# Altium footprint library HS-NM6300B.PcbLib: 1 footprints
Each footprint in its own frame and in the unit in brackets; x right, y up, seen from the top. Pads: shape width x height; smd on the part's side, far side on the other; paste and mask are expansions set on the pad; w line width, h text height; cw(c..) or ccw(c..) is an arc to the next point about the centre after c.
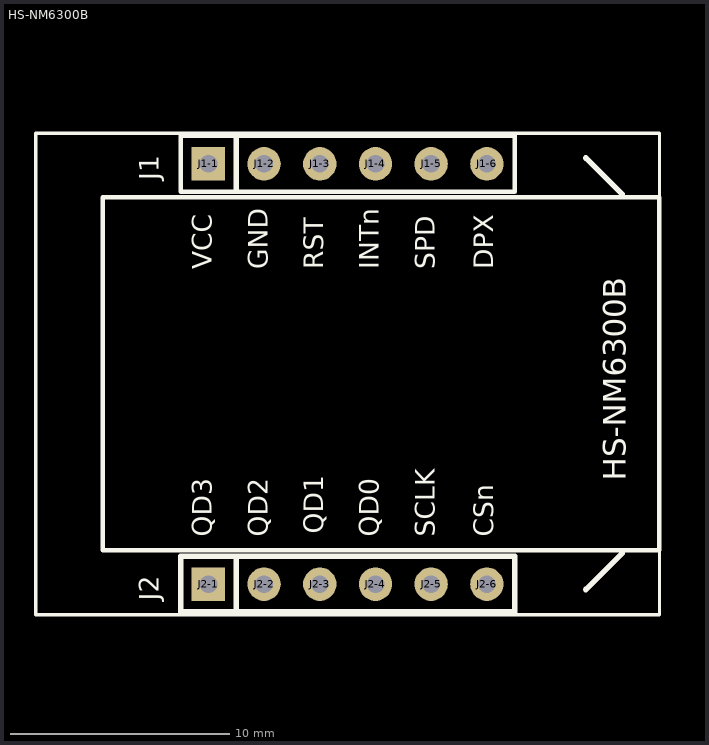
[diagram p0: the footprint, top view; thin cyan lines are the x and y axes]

## HS-NM6300B [mil]
pads (12):
  rect 60x60 hole 32: J1-1(-39967.9,-31115.46) J2-1(-39967.9,-31870.46)
  round 60 hole 32: J1-2(-39867.9,-31115.46) J1-3(-39767.9,-31115.46) J1-4(-39667.9,-31115.46) J1-5(-39567.9,-31115.46) J1-6(-39467.9,-31115.46) J2-2(-39867.9,-31870.46) J2-3(-39767.9,-31870.46) J2-4(-39667.9,-31870.46) J2-5(-39567.9,-31870.46) J2-6(-39467.9,-31870.46)
Top Overlay:
  lines w6: -40277.9,-31925.46 -40277.9,-31060.46 -39157.9,-31060.46 -39157.9,-31925.46 -40277.9,-31925.46
  lines w7.87: -40017.9,-31165.46 -40017.9,-31065.46 -39417.9,-31065.46 -39417.9,-31165.46 -40017.9,-31165.46
  lines w8: -40157.9,-31809.46 -40157.9,-31175.46 -39157.9,-31175.46 -39157.9,-31809.46 -40157.9,-31809.46
  lines w10: -39917.9,-31920.46 -39917.9,-31820.46 ; -39917.9,-31160 -39917.9,-31065.46 ; -39290,-31880 -39225,-31815 ; -39290,-31105 -39225,-31170 ; -40017.9,-31920.46 -39417.9,-31920.46 -39417.9,-31820.46 -40017.9,-31820.46 -40017.9,-31920.46
  text "CSn" at -39445,-31785 h60
  text "SCLK" at -39550,-31785 h60
  text "QD0" at -39650,-31785 h60
  text "QD1" at -39750,-31780 h60
  text "QD2" at -39850,-31785 h60
  text "QD3" at -39950,-31785 h60
  text "DPX" at -39445,-31305 h60
  text "SPD" at -39550,-31305 h60
  text "INTn" at -39650,-31305 h60
  text "RST" at -39750,-31305 h60
  text "GND" at -39850,-31305 h60
  text "VCC" at -39950,-31305 h60
  text "HS-NM6300B" at -39205,-31685 h70
  text "J2" at -40045,-31900 h60
  text "J1" at -40045,-31145 h60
